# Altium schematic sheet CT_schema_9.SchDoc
size 274 x 160 mm
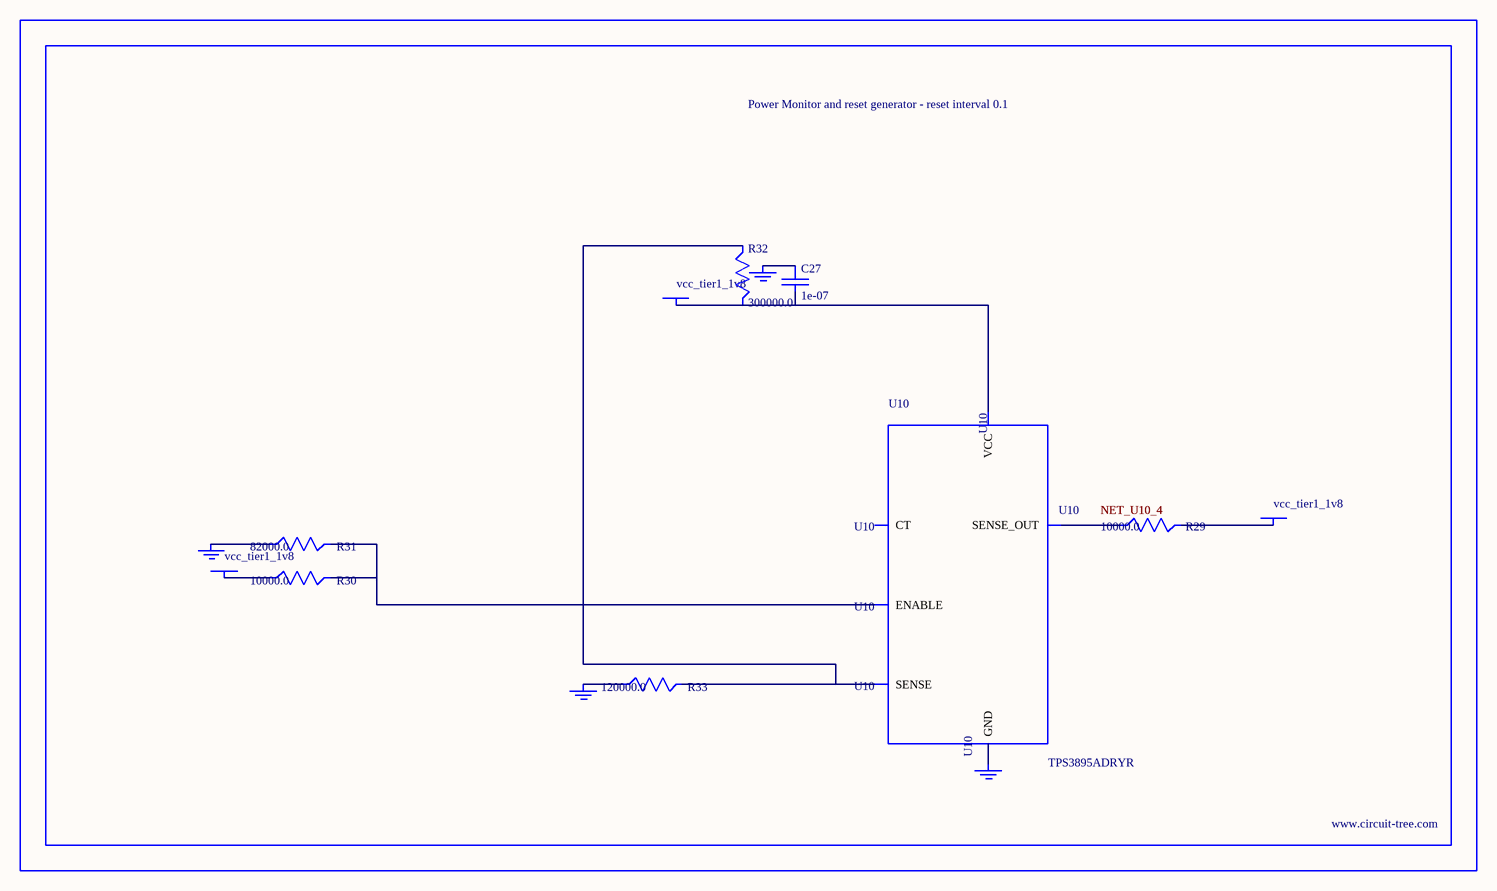
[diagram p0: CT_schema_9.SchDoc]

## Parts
BORDER8  (no value)
C27  1e-07  [C0402]
GND_INSTANCE_8_0  (no value)
GND_INSTANCE_8_1  (no value)
GND_INSTANCE_8_2  (no value)
GND_INSTANCE_8_3  (no value)
POWER_INSTANCE_8_0  vcc_tier1_1v8
POWER_INSTANCE_8_1  vcc_tier1_1v8
POWER_INSTANCE_8_2  vcc_tier1_1v8
R29  10000.0  [R0603]
R30  10000.0  [R0603]
R31  82000.0  [R0603]
R32  300000.0  [R0603]
R33  120000.0  [R0603]
U10  TPS3895ADRYR  [SON-6]

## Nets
NetC27_1: C27.1 GND_INSTANCE_8_2.0(GND)
NetC27_2: C27.2 POWER_INSTANCE_8_2.0(PWR) R32.2 U10.6(VCC)
NetGND_INSTANCE_8_0_0: GND_INSTANCE_8_0.0(GND) R31.1
NetGND_INSTANCE_8_1_0: GND_INSTANCE_8_1.0(GND) R33.1
NetGND_INSTANCE_8_3_0: GND_INSTANCE_8_3.0(GND) U10.2(GND)
NetPOWER_INSTANCE_8_0_0: POWER_INSTANCE_8_0.0(PWR) R30.1
NetPOWER_INSTANCE_8_1_0: POWER_INSTANCE_8_1.0(PWR) R29.2
NetR29_1: R29.1 U10.4(SENSE_OUT)
NetR30_2: R30.2 R31.2 U10.1(ENABLE)
NetR32_1: R32.1 R33.2 U10.3(SENSE)

Not connected (* = marked no-connect by the designer): U10 5(CT)

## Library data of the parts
BORDER8 = BORDER_PAGE8
C27 = C0402C104K3RACTU
GND_INSTANCE_8_0-GND_INSTANCE_8_3 = GND
POWER_INSTANCE_8_0-POWER_INSTANCE_8_2 = PWR
R29 R30 = RC0603JR-0710KL
R31 = RC0603JR-0782KL
R32 = RC0603JR-07300KL
R33 = RC0603JR-07120KL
